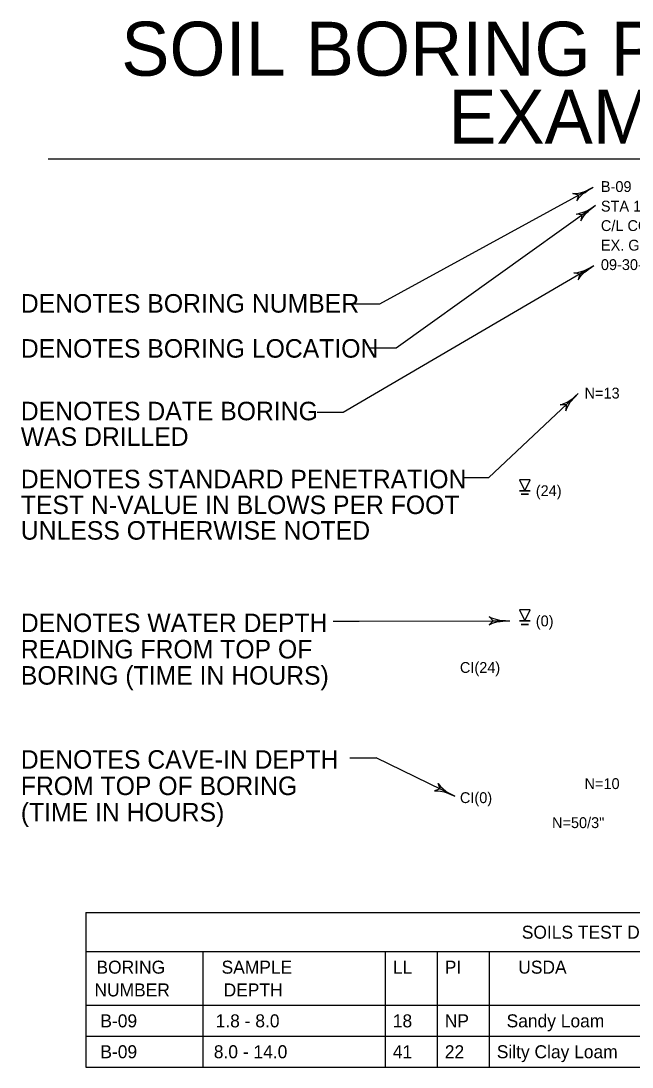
# Model space of a CAD drawing. Extents: x 1.3 to 42.5, y 0 to 21.2.
# Drawn here: x 19.47 to 23.44, y 5.49 to 12.28 of the extents above; entities that cross this region are included whole.
import ezdxf

# ---------------------------------------------------------------- set-up
doc = ezdxf.new("R2010")
doc.units = 0
doc.layers.add('SOIL-BORE', color=7, linetype='Continuous')

msp = doc.modelspace()

# ---------------------------------------------------------------- linework, layer by layer
at = {"layer": 'SOIL-BORE'}
for p, q in [((19.6501, 11.3816), (26.8821, 11.3816)), ((21.8009, 10.4403), (23.1832, 11.1966)), ((23.0885, 11.1451), (23.1833, 11.1969)), ((23.1579, 11.1845), (23.1833, 11.1969)), ((23.1579, 11.1815), (23.1833, 11.1969)), ((23.1833, 11.1969), (23.1833, 11.1969)), ((23.0885, 11.1451), (23.0521, 11.1559)), ((23.0521, 11.1559), (23.0629, 11.1555)), ((23.0629, 11.1555), (23.0775, 11.1571)), ((23.0775, 11.1571), (23.0995, 11.1617)), ((23.0885, 11.1451), (23.0779, 11.1083)), ((23.0837, 11.1175), (23.0917, 11.1283)), ((23.0917, 11.1283), (23.1021, 11.1401)), ((23.0995, 11.1617), (23.1223, 11.1679)), ((23.1021, 11.1401), (23.1195, 11.1559)), ((23.1195, 11.1559), (23.1309, 11.1633)), ((23.1223, 11.1679), (23.1435, 11.1765)), ((23.1309, 11.1633), (23.1455, 11.1731)), ((23.1435, 11.1765), (23.1579, 11.1845)), ((23.1455, 11.1731), (23.1579, 11.1815)), ((21.9072, 10.1561), (23.1984, 11.0799)), ((23.0779, 11.1083), (23.0837, 11.1175)), ((23.1107, 11.0173), (23.1987, 11.0799)), ((23.1617, 11.0551), (23.1747, 11.0645)), ((23.1639, 11.0519), (23.1751, 11.0615)), ((23.1747, 11.0645), (23.1987, 11.0799)), ((23.1751, 11.0615), (23.1987, 11.0799)), ((23.1987, 11.0799), (23.1987, 11.0799)), ((23.0731, 11.0235), (23.0839, 11.0245)), ((23.1107, 11.0173), (23.0731, 11.0235)), ((23.0839, 11.0245), (23.0979, 11.0281)), ((23.0979, 11.0281), (23.1195, 11.0351)), ((23.1107, 11.0173), (23.1045, 10.9795)), ((23.1045, 10.9795), (23.1091, 10.9895)), ((23.1091, 10.9895), (23.1157, 11.0009)), ((23.1157, 11.0009), (23.1247, 11.0137)), ((23.1195, 11.0351), (23.1415, 11.0441)), ((23.1247, 11.0137), (23.1403, 11.0317)), ((23.1403, 11.0317), (23.1503, 11.0405)), ((23.1415, 11.0441), (23.1617, 11.0551)), ((23.1503, 11.0405), (23.1639, 11.0519)), ((21.563, 9.7381), (23.1883, 10.689)), ((23.0841, 10.6453), (23.1061, 10.6507)), ((23.0961, 10.6333), (23.1885, 10.6893)), ((23.1061, 10.6507), (23.1285, 10.6579)), ((23.1265, 10.6455), (23.1373, 10.6537)), ((23.1285, 10.6579), (23.1495, 10.6673)), ((23.1373, 10.6537), (23.1517, 10.6639)), ((23.1495, 10.6673), (23.1635, 10.6757)), ((23.1517, 10.6639), (23.1635, 10.6727)), ((23.1635, 10.6757), (23.1885, 10.6893)), ((23.1635, 10.6727), (23.1885, 10.6893)), ((23.1885, 10.6893), (23.1885, 10.6893)), ((23.0589, 10.6425), (23.0699, 10.6429)), ((23.0961, 10.6333), (23.0589, 10.6425)), ((23.0699, 10.6429), (23.0841, 10.6453)), ((23.0961, 10.6333), (23.0869, 10.5963)), ((23.0869, 10.5963), (23.0921, 10.6059)), ((23.0921, 10.6059), (23.0995, 10.6169)), ((23.0995, 10.6169), (23.1095, 10.6291)), ((23.1095, 10.6291), (23.1265, 10.6455)), ((21.6322, 10.4403), (21.8009, 10.4403)), ((21.7385, 10.1561), (21.9072, 10.1561)), ((23.0868, 9.8592), (22.5078, 9.3161)), ((23.0083, 9.7855), (23.0869, 9.8593)), ((23.0537, 9.8299), (23.0653, 9.8409)), ((23.0563, 9.8269), (23.0663, 9.8379)), ((23.0653, 9.8409), (23.0869, 9.8593)), ((23.0663, 9.8379), (23.0869, 9.8593)), ((23.0869, 9.8593), (23.0869, 9.8593)), ((22.9699, 9.7867), (22.9807, 9.7893)), ((23.0083, 9.7855), (22.9699, 9.7867)), ((22.9807, 9.7893), (22.9943, 9.7945)), ((22.9943, 9.7945), (23.0145, 9.8045)), ((23.0083, 9.7855), (23.0069, 9.7473)), ((23.0103, 9.7577), (23.0153, 9.7699)), ((23.0145, 9.8045), (23.0351, 9.8161)), ((23.0153, 9.7699), (23.0227, 9.7839)), ((23.0227, 9.7839), (23.0355, 9.8037)), ((23.0351, 9.8161), (23.0537, 9.8299)), ((23.0355, 9.8037), (23.0445, 9.8139)), ((23.0445, 9.8139), (23.0563, 9.8269)), ((21.3942, 9.7381), (21.563, 9.7381)), ((23.0069, 9.7473), (23.0103, 9.7577)), ((22.3391, 9.3161), (22.5078, 9.3161)), ((22.5355, 8.3865), (22.5085, 8.4135)), ((22.5085, 8.4135), (22.5179, 8.4081)), ((21.4982, 8.3844), (21.6669, 8.3844)), ((21.6669, 8.3844), (22.6435, 8.3865)), ((22.5355, 8.3865), (22.5089, 8.3595)), ((22.5089, 8.3595), (22.5183, 8.3649)), ((22.5179, 8.4081), (22.5315, 8.4027)), ((22.5183, 8.3649), (22.5301, 8.3703)), ((22.5301, 8.3703), (22.5449, 8.3757)), ((22.5315, 8.4027), (22.5531, 8.3959)), ((22.5355, 8.3865), (22.6435, 8.3867)), ((22.5449, 8.3757), (22.5679, 8.3811)), ((22.5531, 8.3959), (22.5761, 8.3905)), ((22.5679, 8.3811), (22.5815, 8.3823)), ((22.5761, 8.3905), (22.5989, 8.3881)), ((22.5815, 8.3823), (22.5989, 8.3839)), ((22.5989, 8.3881), (22.6151, 8.3881)), ((22.5989, 8.3839), (22.6139, 8.3853)), ((22.6139, 8.3853), (22.6435, 8.3867)), ((22.6151, 8.3881), (22.6435, 8.3867)), ((22.6435, 8.3867), (22.6435, 8.3867)), ((21.6069, 7.4983), (21.7757, 7.4983)), ((22.2876, 7.2482), (21.7757, 7.4983)), ((22.1907, 7.2959), (22.1783, 7.3317)), ((22.1783, 7.3317), (22.1845, 7.3229)), ((22.1907, 7.2959), (22.1545, 7.2835)), ((22.1545, 7.2835), (22.1653, 7.2841)), ((22.1653, 7.2841), (22.1789, 7.2837)), ((22.1789, 7.2837), (22.1945, 7.2819)), ((22.1845, 7.3229), (22.1943, 7.3121)), ((22.1907, 7.2959), (22.2877, 7.2483)), ((22.1943, 7.3121), (22.2107, 7.2967)), ((22.1945, 7.2819), (22.2175, 7.2767)), ((22.2107, 7.2967), (22.2289, 7.2815)), ((22.2175, 7.2767), (22.2301, 7.2721)), ((22.2289, 7.2815), (22.2483, 7.2691)), ((22.2301, 7.2721), (22.2467, 7.2657)), ((22.2467, 7.2657), (22.2605, 7.2603)), ((22.2483, 7.2691), (22.2629, 7.2621)), ((22.2605, 7.2603), (22.2877, 7.2483)), ((22.2629, 7.2621), (22.2877, 7.2483)), ((22.2877, 7.2483), (22.2877, 7.2483)), ((19.8937, 6.4947), (26.8125, 6.4947)), ((19.8937, 6.4947), (19.8937, 6.2416)), ((19.8937, 6.2416), (26.8125, 6.2416)), ((19.8937, 6.2416), (19.8937, 6.0412)), ((20.6531, 6.2416), (20.6531, 6.0412)), ((21.8343, 6.2416), (21.8343, 6.0412)), ((22.1718, 6.2416), (22.1718, 6.0412)), ((22.5093, 6.2416), (22.5093, 6.0412)), ((19.8937, 6.0939), (19.8937, 5.8935)), ((20.6531, 6.0939), (20.6531, 5.8935)), ((21.8343, 6.0939), (21.8343, 5.8935)), ((22.1718, 6.0939), (22.1718, 5.8935)), ((22.5093, 6.0939), (22.5093, 5.8935)), ((19.8937, 5.8935), (26.8125, 5.8935)), ((19.8937, 5.8935), (19.8937, 5.6931)), ((20.6531, 5.8935), (20.6531, 5.6931)), ((21.8343, 5.8935), (21.8343, 5.6931)), ((22.1718, 5.8935), (22.1718, 5.6931)), ((22.5093, 5.8935), (22.5093, 5.6931)), ((19.8937, 5.6931), (26.8125, 5.6931)), ((19.8937, 5.6931), (19.8937, 5.4927)), ((20.6531, 5.6931), (20.6531, 5.4927)), ((21.8343, 5.6931), (21.8343, 5.4927)), ((22.1718, 5.6931), (22.1718, 5.4927)), ((22.5093, 5.6931), (22.5093, 5.4927)), ((19.8937, 5.4927), (26.8125, 5.4927))]:
    msp.add_line(p, q, dxfattribs=at)
for points in [[(22.7408, 9.2297), (22.776, 9.3001), (22.7057, 9.3001)], [(22.7057, 9.2297), (22.7057, 9.2297), (22.776, 9.2297)], [(22.7174, 9.2063), (22.7174, 9.2063), (22.7643, 9.2063)], [(22.7408, 8.386), (22.776, 8.4563), (22.7057, 8.4563)], [(22.7057, 8.386), (22.7057, 8.386), (22.776, 8.386)], [(22.7174, 8.3626), (22.7174, 8.3626), (22.7643, 8.3626)]]:
    msp.add_lwpolyline(points, close=True, dxfattribs=at)

# ---------------------------------------------------------------- texts
for s, height, p in [('SOIL BORING PROFILE', 0.35, (20.1241, 11.9203)), ('EXAMPLE', 0.35, (22.2443, 11.4803)), ('B-09', 0.07031, (23.2337, 11.1663)), ('STA 123+45,20 RT', 0.070308, (23.2337, 11.0393)), ('C/L CONST. MD 650', 0.070308, (23.2337, 10.9133)), ('EX. GRD. ELEV.  125+/-', 0.070308, (23.2337, 10.7863)), ('09-30-2002', 0.07031, (23.2337, 10.6603)), ('DENOTES BORING NUMBER', 0.12, (19.4727, 10.3843)), ('DENOTES BORING LOCATION', 0.12, (19.4727, 10.0923)), ('N=13', 0.07031, (23.1277, 9.8273)), ('DENOTES DATE BORING', 0.12, (19.4727, 9.6863)), ('WAS DRILLED', 0.12, (19.4727, 9.5203)), ('DENOTES STANDARD PENETRATION', 0.12, (19.4727, 9.2453)), ('(24)', 0.07031, (22.8117, 9.1943)), ('TEST N-VALUE IN BLOWS PER FOOT', 0.12, (19.4727, 9.0783)), ('UNLESS OTHERWISE NOTED', 0.12, (19.4727, 8.9123)), ('DENOTES WATER DEPTH ', 0.12, (19.4727, 8.3133)), ('(0)', 0.07031, (22.8117, 8.3503)), ('READING FROM TOP OF', 0.12, (19.4727, 8.1423)), ('BORING (TIME IN HOURS) ', 0.12, (19.4727, 7.9723)), ('CI(24)', 0.07031, (22.3197, 8.0483)), ('DENOTES CAVE-IN DEPTH', 0.12, (19.4727, 7.4273)), ('FROM TOP OF BORING', 0.12, (19.4727, 7.2563)), ('N=10', 0.07031, (23.1277, 7.2953)), ('CI(0)', 0.07031, (22.3197, 7.2043)), ('(TIME IN HOURS)', 0.12, (19.4727, 7.0853)), ('N=50/3"', 0.07031, (22.9167, 7.0423)), ('SOILS TEST DATA', 0.08437, (22.7208, 6.3251)), (' BORING', 0.08437, (19.932, 6.0983)), ('SAMPLE', 0.08437, (20.7744, 6.0983)), (' LL', 0.08437, (21.8532, 6.0983)), (' PI', 0.08437, (22.1904, 6.0983)), ('USDA', 0.08437, (22.698, 6.0983)), (' NUMBER ', 0.08437, (19.9188, 5.9507)), ('DEPTH', 0.08437, (20.7876, 5.9507)), (' B-09', 0.08437, (19.9572, 5.7503)), ('1.8 - 8.0', 0.08437, (20.736, 5.7503)), (' 18', 0.08437, (21.8532, 5.7503)), (' NP', 0.08437, (22.1904, 5.7503)), ('Sandy Loam', 0.08437, (22.6224, 5.7503)), (' B-09', 0.08437, (19.9572, 5.5499)), ('8.0 - 14.0', 0.08437, (20.724, 5.5499)), (' 41', 0.08437, (21.8532, 5.5499)), (' 22', 0.08437, (22.1904, 5.5499)), ('Silty Clay Loam', 0.08437, (22.5588, 5.5499))]:
    msp.add_text(s, height=height, dxfattribs=at).set_placement(p)

doc.saveas('drawing.dxf')
